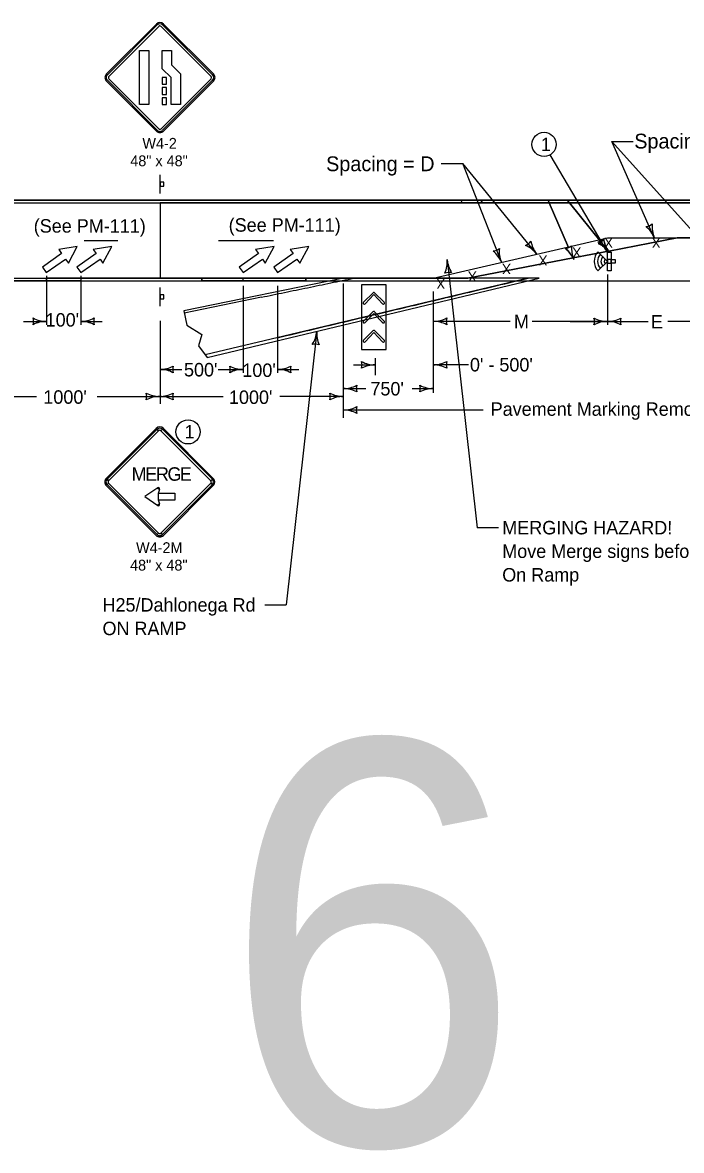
# Model space of a CAD drawing. Extents: x 10133 to 2270741, y 5363 to 1733450.
# Drawn here: x 29175 to 30154, y 10401 to 12076 of the extents above; entities that cross this region are included whole.
import ezdxf

# ---------------------------------------------------------------- set-up
doc = ezdxf.new("R2010")
doc.units = 0
for name, color, linetype in [('dsnNonPlotable', 7, 'Continuous'), ('dsnShtPlotShapeBatchPrint', 7, 'Continuous'), ('dsnStdBlockModified', 7, 'Continuous'), ('dsnStdBorder', 7, 'Continuous'), ('dsnStdNote', 7, 'Continuous'), ('Level 12', 7, 'Continuous'), ('Level 2', 7, 'Continuous'), ('SheetBorder', 7, 'Continuous'), ('SheetText', 7, 'Continuous')]:
    doc.layers.add(name, color=color, linetype=linetype)

msp = doc.modelspace()

# ---------------------------------------------------------------- linework, layer by layer
at = {"layer": 'dsnNonPlotable'}
for p, q in [((29785, 11696.6), (30043.8, 11756.4)), ((30043.8, 11756.4), (30192, 11756.4)), ((29232.6, 11733.2), (29204, 11713.1)), ((29256, 11743.4), (29228.3, 11739.3)), ((29228.3, 11739.3), (29232.6, 11733.2)), ((29242.7, 11718.8), (29256, 11743.4)), ((29283.9, 11733.2), (29255.3, 11713.1)), ((29307.3, 11743.4), (29279.6, 11739.3)), ((29279.6, 11739.3), (29283.9, 11733.2)), ((29294, 11718.8), (29307.3, 11743.4)), ((29525.3, 11733.2), (29496.6, 11713.1)), ((29548.6, 11743.4), (29521, 11739.3)), ((29521, 11739.3), (29525.3, 11733.2)), ((29535.3, 11718.8), (29548.6, 11743.4)), ((29576.6, 11733.2), (29547.9, 11713.1)), ((29599.9, 11743.4), (29572.3, 11739.3)), ((29572.3, 11739.3), (29576.6, 11733.2)), ((29586.6, 11718.8), (29599.9, 11743.4)), ((29204, 11713.1), (29209.7, 11704.9)), ((29209.7, 11704.9), (29238.4, 11725)), ((29238.4, 11725), (29242.7, 11718.8)), ((29255.3, 11713.1), (29261, 11704.9)), ((29261, 11704.9), (29289.7, 11725)), ((29289.7, 11725), (29294, 11718.8)), ((29496.6, 11713.1), (29502.3, 11704.9)), ((29502.3, 11704.9), (29531, 11725)), ((29531, 11725), (29535.3, 11718.8)), ((29547.9, 11713.1), (29553.6, 11704.9)), ((29553.6, 11704.9), (29582.3, 11725)), ((29582.3, 11725), (29586.6, 11718.8)), ((28169.7, 11696.6), (29666.9, 11696.6)), ((29926, 11696.6), (29446, 11582.6)), ((29529.6, 11668.3), (29414.9, 11644.6))]:
    msp.add_line(p, q, dxfattribs=at)
for points in [[(28161.8, 11808.6), (30191.3, 11808.6)], [(29266, 11752.6), (29316, 11752.6)], [(29266, 11752.6), (29316, 11752.6)], [(29465.9, 11752.6), (29515.9, 11752.6)], [(29497.7, 11752.6), (29547.7, 11752.6)]]:
    msp.add_lwpolyline(points, dxfattribs=at)
for points in [[(29529.6, 11668.3), (29666.8, 11696.6)], [(29555, 11608.5), (29926, 11696.6)]]:
    msp.add_open_spline(points, degree=1, dxfattribs=at)
at = {"layer": 'dsnShtPlotShapeBatchPrint'}
msp.add_circle((29420.6, 11468.2), 18, dxfattribs=at)
at = {"layer": 'dsnStdBlockModified'}
for p, q in [((30029.7, 11735.6), (30043.9, 11721.5)), ((30049.5, 11735.2), (30043.9, 11735.2)), ((30043.9, 11721.5), (30029.7, 11707.3)), ((30049.5, 11707.7), (30043.9, 11707.7))]:
    msp.add_line(p, q, dxfattribs=at)
for radius, start, end in [(20.3, 135.88, 224.0313), (15.3, 136.1665, 223.7159), (10.3, 136.7294, 223.0963), (5.32, 138.7005, 221.2995)]:
    msp.add_arc((30044.3, 11721.5), radius, start, end, dxfattribs=at)
at = {"layer": 'dsnStdBorder'}
for p, q in [((29373.5, 12074.1), (29299.3, 11999.9)), ((29299.3, 11999.9), (29373.5, 12074.1)), ((29374.8, 12072.8), (29300.6, 11998.5)), ((29302.8, 11996.3), (29377, 12070.6)), ((29380.6, 12070.6), (29380.6, 12070.6)), ((29380.6, 12070.6), (29454.8, 11996.3)), ((29457, 11998.5), (29382.8, 12072.8)), ((29458.4, 11999.9), (29384.1, 12074.1)), ((29384.1, 12074.1), (29458.4, 11999.9)), ((29384.1, 12074.1), (29384.1, 12074.1)), ((29299.3, 11989.3), (29373.5, 11915)), ((29373.5, 11915), (29299.3, 11989.3)), ((29300.6, 11990.6), (29374.8, 11916.3)), ((29377, 11918.6), (29302.8, 11992.8)), ((29454.8, 11992.8), (29380.6, 11918.6)), ((29382.8, 11916.3), (29457, 11990.6)), ((29384.1, 11915), (29458.4, 11989.3)), ((29458.4, 11989.3), (29384.1, 11915)), ((29379, 11822.6), (29379, 11850.1)), ((30043.8, 11708), (30043.8, 11735.5)), ((30049.5, 11735.2), (30049.5, 11707.7)), ((29379, 11655.1), (29379, 11682.6)), ((29697.7, 11674.9), (29711.8, 11660.8)), ((29697.7, 11646.8), (29711.8, 11632.7)), ((29697.7, 11618.6), (29711.8, 11604.5)), ((29373.2, 11473.4), (29298.9, 11399.1)), ((29374.5, 11472.1), (29376.7, 11469.9)), ((29380.2, 11469.9), (29382.4, 11472.1)), ((29458, 11399.1), (29383.8, 11473.4)), ((29302.5, 11395.6), (29300.2, 11397.8)), ((29456.7, 11397.8), (29454.5, 11395.6)), ((29298.9, 11388.5), (29373.2, 11314.3)), ((29300.2, 11389.9), (29302.5, 11392.1)), ((29375.4, 11385.2), (29376.4, 11383.5)), ((29376.4, 11383.5), (29378.4, 11382.9)), ((29383.8, 11314.3), (29458, 11388.5)), ((29454.5, 11392.1), (29456.7, 11389.9)), ((29378.4, 11361), (29376.4, 11360.4)), ((29376.4, 11360.4), (29375.4, 11358.7)), ((29376.7, 11317.8), (29374.5, 11315.6)), ((29382.4, 11315.6), (29380.2, 11317.8))]:
    msp.add_line(p, q, dxfattribs=at)
for points in [[(29300.6, 11998.5), (29374.8, 12072.8)], [(29302.8, 11996.3), (29377, 12070.6)], [(29380.6, 12070.6), (29454.8, 11996.3)], [(29382.8, 12072.8), (29457, 11998.5)], [(29374.8, 11916.3), (29300.6, 11990.6)], [(29377, 11918.6), (29302.8, 11992.8)], [(29454.8, 11992.8), (29380.6, 11918.6)], [(29457, 11990.6), (29382.8, 11916.3)], [(29681.3, 11660.8), (29681.3, 11660.8), (29695.4, 11674.9), (29695.4, 11674.9)], [(29709.5, 11658.5), (29709.5, 11658.5), (29696.6, 11672.1), (29683.7, 11658.5)], [(29681.3, 11632.7), (29681.3, 11632.8), (29695.4, 11646.9), (29695.4, 11646.9)], [(29709.5, 11630.4), (29709.5, 11630.5), (29696.6, 11644), (29683.7, 11630.5)], [(29681.3, 11604.5), (29681.3, 11604.5), (29695.4, 11618.6), (29695.4, 11618.6)], [(29709.5, 11602.2), (29709.5, 11602.2), (29696.6, 11615.8), (29683.7, 11602.2)]]:
    msp.add_lwpolyline(points, dxfattribs=at)
for points in [[(29362.1, 12034.6), (29362.1, 11954.6), (29348.6, 11954.6), (29348.6, 12034.6)], [(29395.8, 12013.4), (29409.1, 12000.2), (29409.1, 11954.6), (29395.6, 11954.6), (29395.6, 11994.6), (29382.3, 12007.8), (29382.3, 12034.6), (29395.8, 12034.6)], [(29388.3, 11994.6), (29382.3, 11994.6), (29382.3, 11984.6), (29388.3, 11984.6)], [(29388.3, 11979.6), (29382.3, 11979.6), (29382.3, 11969.6), (29388.3, 11969.6)], [(29388.3, 11964.6), (29382.3, 11964.6), (29382.3, 11954.6), (29388.3, 11954.6)], [(29379.1, 11839.1), (29379.1, 11833.4), (29384.7, 11833.4), (29384.7, 11839.1)], [(30043.9, 11707.7), (30043.9, 11735.2), (30049.5, 11735.2), (30049.5, 11707.7)], [(30043.9, 11724.4), (30043.9, 11718.8), (30049.5, 11718.8), (30049.5, 11724.4)], [(30049.5, 11718.8), (30049.5, 11724.4), (30055.1, 11724.4), (30055.1, 11718.8)], [(29714.9, 11590.5), (29714.9, 11686.5), (29678.2, 11686.5), (29678.2, 11590.5)], [(29379.1, 11671.6), (29379.1, 11665.9), (29384.7, 11665.9), (29384.7, 11671.6)], [(29374.5, 11472.1), (29300.2, 11397.8), (29302.5, 11395.6), (29376.7, 11469.9), (29374.5, 11472.1)], [(29456.7, 11397.8), (29382.4, 11472.1), (29380.2, 11469.9), (29454.5, 11395.6), (29456.7, 11397.8)], [(29300.2, 11389.9), (29374.5, 11315.6), (29376.7, 11317.8), (29302.5, 11392.1), (29300.2, 11389.9)], [(29356.1, 11372), (29375.4, 11358.7), (29376.4, 11360.4), (29378.4, 11361), (29376.4, 11367), (29376.4, 11377), (29378.4, 11382.9), (29376.4, 11383.5), (29375.4, 11385.2), (29356.1, 11372)], [(29382.4, 11315.6), (29456.7, 11389.9), (29454.5, 11392.1), (29380.2, 11317.8), (29382.4, 11315.6)], [(29400.8, 11377), (29400.8, 11367), (29376.4, 11367), (29376.4, 11377), (29400.8, 11377)]]:
    msp.add_lwpolyline(points, close=True, dxfattribs=at)
for centre, radius, start, end in [((29378.8, 12068.8), 7.5, 45, 134.9997), ((29378.8, 12068.8), 7.5, 45, 134.9997), ((29378.8, 12068.8), 5.63, 45, 134.9997), ((29378.8, 12068.8), 5.63, 45, 134.9997), ((29378.8, 12068.8), 2.5, 45, 134.9997), ((29378.8, 12068.8), 2.5, 45, 134.9997), ((29304.6, 11994.6), 7.5, 134.9997, 225), ((29304.6, 11994.6), 7.5, 134.9997, 225), ((29304.6, 11994.6), 5.63, 134.9997, 225), ((29304.6, 11994.6), 5.63, 134.9997, 225), ((29453.1, 11994.6), 5.63, 315.0002, 44.9998), ((29453.1, 11994.6), 5.63, 315.0002, 44.9998), ((29453.1, 11994.6), 7.5, 315.0002, 44.9998), ((29453.1, 11994.6), 7.5, 315.0002, 44.9998), ((29304.6, 11994.6), 2.5, 134.9997, 225), ((29304.6, 11994.6), 2.5, 134.9997, 225), ((29453.1, 11994.6), 2.5, 315.0002, 44.9998), ((29453.1, 11994.6), 2.5, 315.0002, 44.9998), ((29378.8, 11920.3), 7.5, 225, 315.0002), ((29378.8, 11920.3), 7.5, 225, 315.0002), ((29378.8, 11920.3), 5.63, 225, 315.0002), ((29378.8, 11920.3), 5.63, 225, 315.0002), ((29378.8, 11920.3), 2.5, 225, 315.0002), ((29378.8, 11920.3), 2.5, 225, 315.0002), ((29696.6, 11673.8), 1.65, 44.1616, 134.6098), ((29682.4, 11659.6), 1.65, 136.201, 317.3602), ((29696.6, 11645.7), 1.65, 44.1616, 134.6098), ((29710.7, 11659.6), 1.65, 225.0975, 45.281), ((29682.4, 11631.6), 1.65, 136.201, 317.3602), ((29710.7, 11631.6), 1.65, 225.0975, 45.281), ((29696.6, 11617.5), 1.65, 44.1616, 134.6098), ((29682.4, 11603.3), 1.65, 136.201, 317.3602), ((29710.7, 11603.3), 1.65, 225.0975, 45.281), ((29378.5, 11468.1), 7.5, 45, 134.9997), ((29378.5, 11468.1), 5.62, 45, 134.9997), ((29378.5, 11468.1), 2.5, 45, 134.9997), ((29304.2, 11393.8), 7.5, 134.9997, 225), ((29304.2, 11393.8), 5.62, 134.9997, 225), ((29304.2, 11393.8), 2.5, 134.9997, 225), ((29452.7, 11393.8), 2.5, 315.0002, 44.9998), ((29452.7, 11393.8), 5.62, 315.0002, 44.9998), ((29452.7, 11393.8), 7.5, 315.0002, 44.9998), ((29376.4, 11383.5), 2.03, 341.4187, 122.3124), ((29376.4, 11360.4), 2.03, 237.6875, 18.5819), ((29378.5, 11319.6), 7.5, 225, 315.0002), ((29378.5, 11319.6), 5.62, 225, 315.0002), ((29378.5, 11319.6), 2.5, 225, 315.0002)]:
    msp.add_arc(centre, radius, start, end, dxfattribs=at)
at = {"layer": 'dsnStdNote'}
msp.add_circle((29949.6, 11895.3), 18, dxfattribs=at)
at = {"layer": 'Level 12'}
for p, q in [((30050.1, 11899.7), (30082.1, 11899.7)), ((30113.4, 11756.7), (30050.1, 11899.7)), ((30178.9, 11756.7), (30050.1, 11899.7)), ((29796.8, 11866.8), (29828.8, 11866.8)), ((29938.5, 11732.7), (29828.8, 11866.8)), ((29886.2, 11720.4), (29828.8, 11866.8)), ((30043.8, 11735.5), (29958.7, 11879.8)), ((29805.5, 11724.3), (29849.9, 11325.7)), ((29210.2, 11700), (29210.2, 11627.4)), ((29261, 11700), (29261, 11627.4)), ((30043.8, 11702.2), (30043.8, 11627.4)), ((29502.5, 11685.4), (29502.5, 11556)), ((29553.3, 11685.4), (29553.3, 11556)), ((29651.2, 11688.5), (29651.2, 11489)), ((29785, 11676.6), (29785, 11526.2)), ((29176.2, 11632.4), (29210.2, 11632.4)), ((29261, 11632.4), (29293, 11632.4)), ((29379, 11633.3), (29379, 11509.8)), ((29899, 11632.4), (29785, 11632.4)), ((30045.5, 11632.3), (29932.1, 11632.3)), ((29988.2, 11632.3), (30104.4, 11632.3)), ((30285.8, 11632.3), (30133.6, 11632.3)), ((29611.9, 11617.7), (29566.5, 11211.1)), ((29666.4, 11567.7), (29698.4, 11567.7)), ((29698.4, 11577.9), (29698.4, 11552.7)), ((29837.5, 11567.8), (29785, 11567.8)), ((29379.1, 11561), (29411.3, 11561)), ((29465.5, 11561), (29502.5, 11561)), ((29553.3, 11561), (29585.3, 11561)), ((29651.2, 11532.5), (29684.7, 11532.5)), ((29753.4, 11532.5), (29785, 11532.5)), ((29086.1, 11520.8), (29195.4, 11520.8)), ((29285.6, 11520.8), (29378.3, 11520.8)), ((29378.3, 11520.8), (29378.3, 11520.8)), ((29378.3, 11520.8), (29472.6, 11520.8)), ((29651.2, 11520.8), (29556.9, 11520.8)), ((29858.9, 11500.7), (29651.2, 11500.7)), ((29881.9, 11325.7), (29849.9, 11325.7)), ((29534.5, 11211.1), (29566.5, 11211.1))]:
    msp.add_line(p, q, dxfattribs=at)
for centre, radius, start, end in [((30099.7, 11789.6), 16.4, 274.8945, 310.3612), ((30074.1, 11740.4), 42.5, 22.6279, 50.7004), ((30152.6, 11773.1), 42.5, 174.5554, 202.6279), ((29916.2, 11760.6), 16.4, 290.8549, 326.3216), ((29971.7, 11759.2), 42.5, 190.5158, 218.5882), ((30026.3, 11766.5), 16.4, 281.5553, 317.0221), ((30006.7, 11714.7), 42.5, 29.2887, 57.3612), ((30080.8, 11756.3), 42.5, 181.2162, 209.2887), ((29872.5, 11753.3), 16.4, 274.9287, 310.3954), ((29847, 11704), 42.5, 22.662, 50.7345), ((29925.4, 11736.8), 42.5, 174.5895, 202.662), ((29905.2, 11706.2), 42.5, 38.5882, 66.6607), ((29763.1, 11720.7), 42.5, 336.8126, 4.8851), ((29847.8, 11728), 42.5, 184.8851, 212.9576), ((29808.5, 11688.8), 16.4, 77.1518, 112.6185), ((29174.6, 11632.4), 16.4, 342.2667, 17.7334), ((29210.2, 11674.9), 42.5, 241.9275, 270), ((29210.2, 11589.9), 42.5, 90, 118.0725), ((29261, 11674.9), 42.5, 270, 298.0725), ((29261, 11589.9), 42.5, 61.9275, 90), ((29296.7, 11632.4), 16.4, 162.2666, 197.7334), ((29785, 11674.9), 42.5, 270, 298.0725), ((29785, 11589.9), 42.5, 61.9275, 90), ((29820.7, 11632.4), 16.4, 162.2666, 197.7334), ((30008.1, 11632.3), 16.4, 342.2667, 17.7334), ((30043.8, 11674.8), 42.5, 241.9275, 270), ((30043.8, 11589.8), 42.5, 90, 118.0725), ((30043.8, 11674.8), 42.5, 270, 298.0725), ((30043.8, 11589.8), 42.5, 61.9275, 90), ((30079.4, 11632.3), 16.4, 162.2666, 197.7334), ((29569.5, 11621.3), 42.5, 327.0424, 355.1149), ((29654.2, 11614.1), 42.5, 175.1149, 203.1874), ((29608.8, 11582.2), 16.4, 67.3815, 102.8482), ((29378.5, 11603.5), 42.5, 270, 298.0725), ((29414.2, 11561), 16.4, 162.2666, 197.7334), ((29466.9, 11561), 16.4, 342.2667, 17.7334), ((29502.5, 11603.5), 42.5, 241.9275, 270), ((29553.3, 11603.5), 42.5, 270, 298.0725), ((29589, 11561), 16.4, 162.2666, 197.7334), ((29662.8, 11567.7), 16.4, 342.2667, 17.7334), ((29698.4, 11610.2), 42.5, 241.9275, 270), ((29698.4, 11525.2), 42.5, 90, 118.0725), ((29785, 11610.3), 42.5, 270, 298.0725), ((29785, 11525.3), 42.5, 61.9275, 90), ((29820.7, 11567.8), 16.4, 162.2666, 197.7334), ((29378.5, 11518.5), 42.5, 61.9275, 90), ((29502.5, 11518.5), 42.5, 90, 118.0725), ((29553.3, 11518.5), 42.5, 61.9275, 90), ((29651.2, 11575), 42.5, 270, 298.0725), ((29651.2, 11490), 42.5, 61.9275, 90), ((29686.8, 11532.5), 16.4, 162.2666, 197.7334), ((29749.4, 11532.5), 16.4, 342.2666, 17.7334), ((29785, 11575), 42.5, 241.9275, 270), ((29785, 11490), 42.5, 90, 118.0725), ((29342.7, 11520.8), 16.4, 342.2667, 17.7334), ((29378.3, 11563.3), 42.5, 241.9275, 270), ((29378.3, 11478.3), 42.5, 90, 118.0725), ((29378.3, 11563.3), 42.5, 270, 298.0725), ((29378.3, 11478.3), 42.5, 61.9275, 90), ((29414, 11520.8), 16.4, 162.2666, 197.7334), ((29615.5, 11520.8), 16.4, 342.2667, 17.7334), ((29651.2, 11563.3), 42.5, 241.9275, 270), ((29651.2, 11478.3), 42.5, 90, 118.0725), ((29651.2, 11543.2), 42.5, 270, 298.0725), ((29651.2, 11458.2), 42.5, 61.9275, 90), ((29686.9, 11500.7), 16.4, 162.2666, 197.7334)]:
    msp.add_arc(centre, radius, start, end, dxfattribs=at)
at = {"layer": 'Level 2'}
for p, q in [((28161.8, 11808.6), (29379, 11808.6)), ((28161.8, 11808.6), (29957.3, 11808.6)), ((28165.8, 11812.6), (30292.4, 11812.6)), ((29955.6, 11812.6), (28165.8, 11812.6)), ((29379, 11808.6), (29379, 11696.6)), ((29957.3, 11808.6), (29379, 11808.6)), ((29379, 11808.6), (29379, 11696.6)), ((29826.5, 11812.6), (29855, 11812.6)), ((29828.1, 11808.6), (29826.5, 11812.6)), ((29858.1, 11808.6), (29828.1, 11808.6)), ((29855, 11812.6), (29858.1, 11808.6)), ((29984.1, 11812.6), (29955.6, 11812.6)), ((29955.6, 11812.6), (29957.3, 11808.6)), ((29957.3, 11808.6), (29955.6, 11812.6)), ((29957.3, 11808.6), (29987.3, 11808.6)), ((29986, 11742.1), (29957.3, 11808.6)), ((29987.3, 11808.6), (29957.3, 11808.6)), ((29957.3, 11808.6), (29986, 11742.1)), ((30194.5, 11812.6), (29984.1, 11812.6)), ((29984.1, 11812.6), (29987.3, 11808.6)), ((29987.3, 11808.6), (29984.1, 11812.6)), ((29987.3, 11808.6), (30196.1, 11808.6)), ((30196.1, 11808.6), (29987.3, 11808.6)), ((29987.3, 11808.6), (30034.6, 11750.3)), ((30034.6, 11750.3), (29987.3, 11808.6)), ((30147.1, 11756.4), (30045.6, 11736.8)), ((30045.6, 11736.8), (30147.1, 11756.4)), ((30262.5, 11756.4), (30147.1, 11756.4)), ((30147.1, 11756.4), (30295.3, 11756.4)), ((30045.5, 11736.8), (29992.7, 11726.7)), ((29992.7, 11726.7), (30045.5, 11736.8)), ((30046.7, 11735.3), (30046.3, 11735.8)), ((29836.4, 11696.6), (29992.6, 11726.6)), ((29992.6, 11726.6), (29836.4, 11696.6)), ((29210.2, 11696.6), (29210.2, 11692.6)), ((29210.2, 11692.6), (29210.2, 11696.6)), ((29210.2, 11696.6), (29261, 11696.6)), ((29502.5, 11696.6), (29261, 11696.6)), ((29261, 11696.6), (29261, 11692.6)), ((29261, 11696.6), (29261, 11692.6)), ((29379, 11696.6), (29440.9, 11696.6)), ((29440.9, 11696.6), (29595.5, 11696.6)), ((29595.5, 11696.6), (29440.9, 11696.6)), ((29440.9, 11696.6), (29440.9, 11692.6)), ((29440.9, 11692.6), (29440.9, 11696.6)), ((29440.9, 11696.6), (29595.5, 11696.6)), ((29502.5, 11692.6), (29502.5, 11696.6)), ((29595.5, 11692.6), (29595.5, 11696.6)), ((29595.5, 11696.6), (29595.5, 11692.6)), ((29595.5, 11696.6), (29836.4, 11696.6)), ((29836.4, 11696.6), (29595.5, 11696.6)), ((29595.5, 11696.6), (29595.5, 11692.6)), ((28165.8, 11692.6), (30498, 11692.6)), ((29210.2, 11692.6), (28165.8, 11692.6)), ((29261, 11692.6), (29210.2, 11692.6)), ((29261, 11692.6), (29502.5, 11692.6)), ((29595.5, 11692.6), (29440.9, 11692.6)), ((29440.9, 11692.6), (29595.5, 11692.6)), ((29595.5, 11692.6), (30426.1, 11692.6))]:
    msp.add_line(p, q, dxfattribs=at)
for points in [[(30045.5, 11736.8), (30045.6, 11736.8)], [(29993.6, 11724.5), (29993.6, 11724.5), (29993.2, 11725.3)], [(29993.2, 11725.3), (29993.2, 11725.3)], [(29379, 11696.6), (29261, 11696.6), (29210.2, 11696.6)]]:
    msp.add_lwpolyline(points, dxfattribs=at)
for centre, radius, start, end in [((30024.5, 11763.2), 16.4, 290.8549, 326.3216), ((30024.5, 11763.2), 16.4, 290.8549, 308.0905), ((30013.5, 11708.8), 42.5, 41.1781, 66.6607), ((30013.5, 11708.8), 42.5, 41.1781, 66.6607), ((30024.5, 11763.2), 16.4, 308.0905, 326.3216), ((30079.9, 11761.8), 42.5, 190.5158, 216.0585), ((30079.9, 11761.8), 42.5, 190.5158, 216.0585), ((29979.8, 11757.3), 16.4, 274.9287, 310.3954), ((29979.8, 11757.3), 16.4, 274.9287, 291.9208), ((29954.3, 11708.1), 42.5, 25.9041, 50.7345), ((29954.3, 11708.1), 42.5, 23.928, 50.7345), ((29979.8, 11757.3), 16.4, 291.9208, 310.3954), ((30032.8, 11740.8), 42.5, 174.5895, 199.4578), ((30032.8, 11740.8), 42.5, 174.5895, 199.4578), ((30013.5, 11708.8), 42.5, 39.4385, 41.1781), ((30079.9, 11761.8), 42.5, 216.0585, 218.5706), ((30013.5, 11708.8), 42.5, 38.5882, 38.6058), ((30079.9, 11761.8), 42.5, 218.5875, 218.5882), ((29954.3, 11708.1), 42.5, 23.928, 25.9041), ((30032.8, 11740.8), 42.5, 199.4578, 202.6444), ((30032.8, 11740.8), 42.5, 199.4578, 201.3966), ((29954.3, 11708.1), 42.5, 22.662, 22.6796)]:
    msp.add_arc(centre, radius, start, end, dxfattribs=at)
at = {"layer": 'SheetBorder'}
for p, q in [((29448.9, 11578.8), (29942.4, 11696.6)), ((29942.4, 11696.6), (29651.4, 11696.6))]:
    msp.add_line(p, q, dxfattribs=at)
for points in [[(29651.4, 11696.6), (29414.2, 11648.2), (29414.2, 11648.2)], [(29414.2, 11648.2), (29418.6, 11626.6), (29440.8, 11613), (29436, 11595.9), (29448.9, 11578.8)]]:
    msp.add_lwpolyline(points, dxfattribs=at)

# ---------------------------------------------------------------- texts
at = {"layer": 'dsnShtPlotShapeBatchPrint'}
msp.add_text('1', height=20, dxfattribs=at).set_placement((29415.4, 11458.5))
at = {"layer": 'dsnStdBorder'}
for s, height, p in [('W4-2', 16, (29352.7, 11888.9)), ('48" x 48"', 16, (29334.7, 11862.9)), ('(See PM-111)', 20, (29191.2, 11764.2)), ('(See PM-111)', 20, (29480.9, 11765.6)), ('M', 20, (29336.6, 11395.6)), ('E', 20, (29356.8, 11395.6)), ('R', 20, (29372.8, 11395.6)), ('G', 20, (29390, 11395.6)), ('E', 20, (29408.2, 11395.6)), ('W4-2M', 16, (29343.3, 11288.2)), ('48" x 48"', 16, (29334.4, 11262.2))]:
    msp.add_text(s, height=height, dxfattribs=at).set_placement(p)
for p in [(30052.2, 11756.9), (30122.9, 11756.9), (29954.7, 11730.7), (30004.8, 11742.5), (29900.4, 11718), (29802.8, 11696), (29849.6, 11706.7)]:
    msp.add_text('X', height=15, rotation=180, dxfattribs=at).set_placement(p)
at = {"layer": 'dsnStdNote'}
msp.add_text('1', height=20, dxfattribs=at).set_placement((29944.8, 11885.3))
at = {"layer": 'Level 12'}
for s, height, p in [('Spacing = D', 22, (30083.6, 11889.2)), ('Spacing = D', 22, (29625.7, 11855.5)), ("100'", 20, (29208.9, 11624.6)), ('M', 20, (29904.7, 11622.1)), ('E', 20, (30108.4, 11621.8)), ("500'", 20, (29414.5, 11550.6)), ("100'", 20, (29501.2, 11549.8)), ("0' - 500'", 20, (29839.4, 11558)), ("1000'", 20, (29205.5, 11510)), ("1000'", 20, (29481.3, 11509.7)), ("750'", 20, (29691.5, 11522.3)), ('Pavement Marking Removal Limits', 20, (29870.2, 11492.1)), ('MERGING HAZARD!', 20, (29887.4, 11315.9)), ('Move Merge signs before', 20, (29887.4, 11280.9)), ('On Ramp', 20, (29887.4, 11245.9)), ('H25/Dahlonega Rd', 20, (29293.4, 11201.2)), ('ON RAMP', 20, (29293.4, 11166.2))]:
    msp.add_text(s, height=height, dxfattribs=at).set_placement(p)
at = {"layer": 'SheetText'}
msp.add_text('6', height=600, dxfattribs=at).set_placement((29470.4, 10409.2))

doc.saveas('drawing.dxf')
